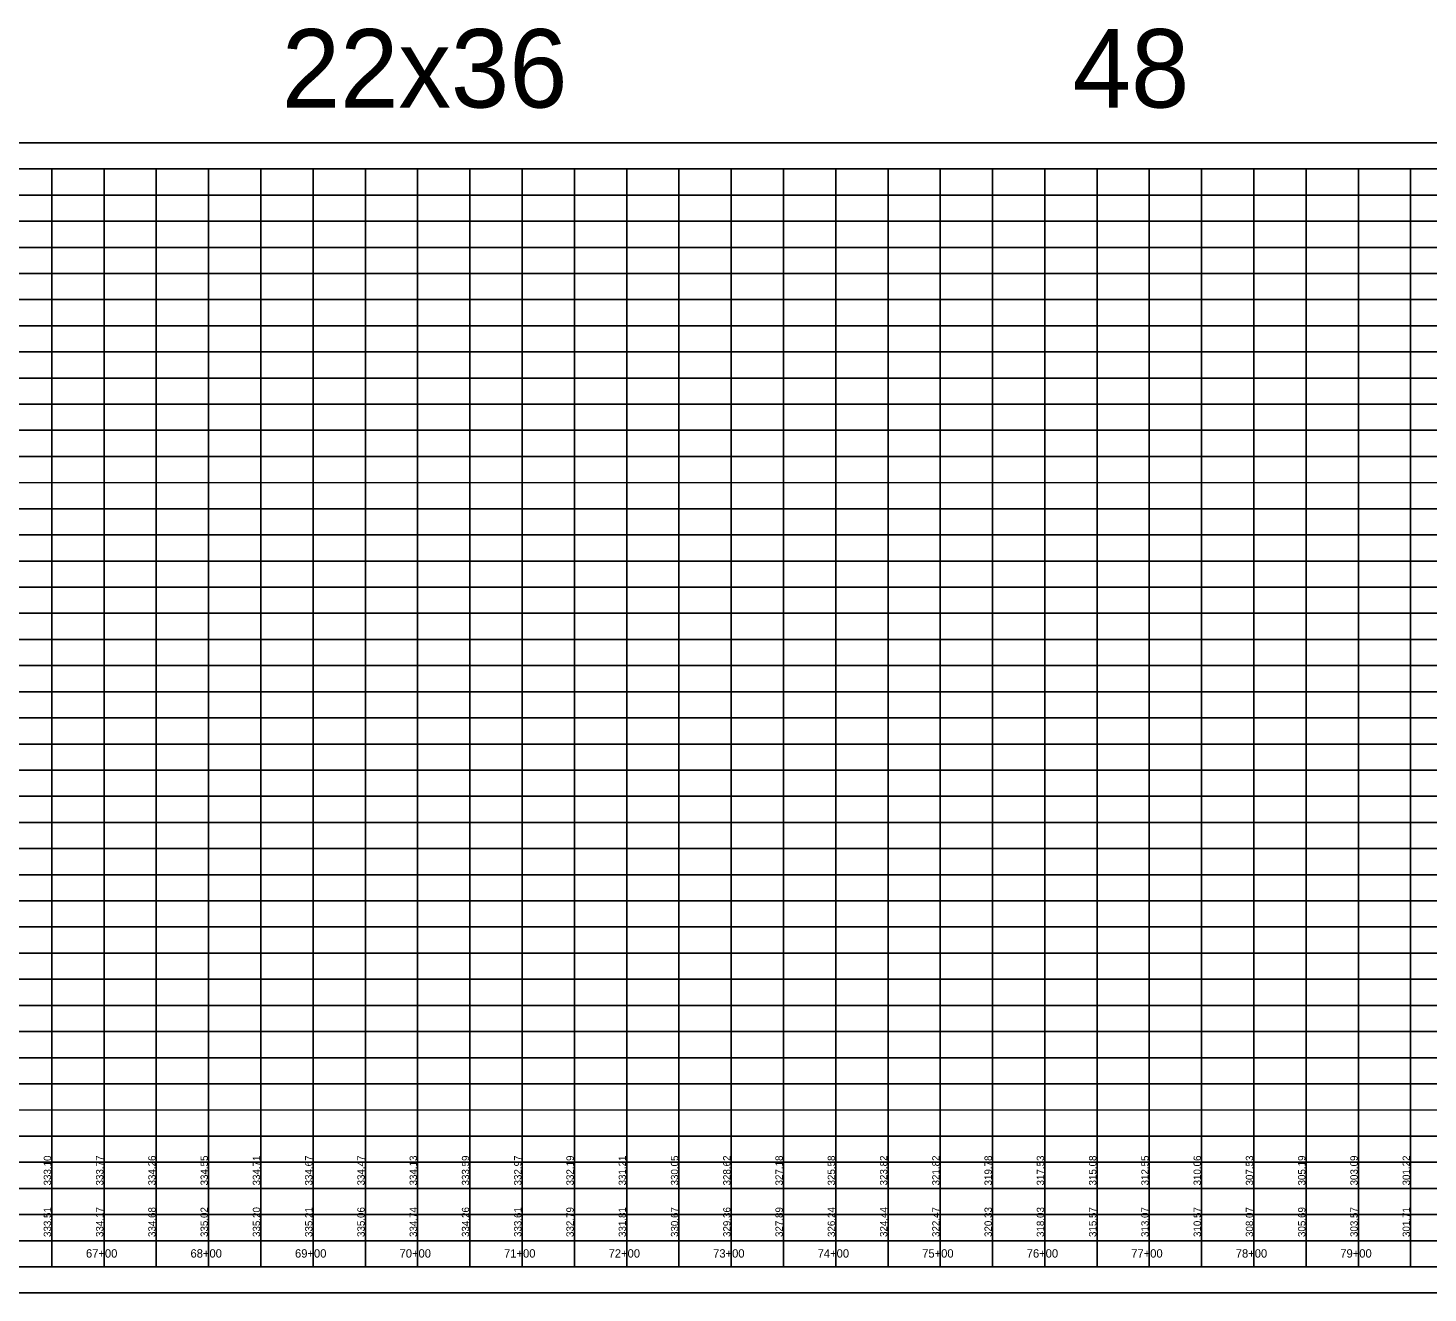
# Model space of a CAD drawing. Extents: x 1873632 to 1926512, y 813126 to 836257.
# Drawn here: x 1884990 to 1886329, y 831005 to 832214 of the extents above; entities that cross this region are included whole.
import ezdxf

# ---------------------------------------------------------------- set-up
doc = ezdxf.new("R2010")
doc.units = 0
for name, color, linetype in [('RD_DDB_StaTX', 7, 'Continuous'), ('RD_DDB_StripGrade', 7, 'Continuous'), ('RD_PD_WallFill', 7, 'Continuous'), ('RD_SHT_IplotShp', 7, 'Continuous')]:
    doc.layers.add(name, color=color, linetype=linetype)

msp = doc.modelspace()

# ---------------------------------------------------------------- linework, layer by layer
at = {"layer": 'RD_PD_WallFill'}
for p, q in [((1883662.8, 832079.6), (1889012.8, 832079.6)), ((1883662.8, 832079.6), (1885412.8, 832079.6)), ((1885012.8, 831029.5), (1885012.8, 832079.6)), ((1885012.8, 831029.5), (1885012.8, 832079.6)), ((1885062.8, 831029.5), (1885062.8, 832079.6)), ((1885062.8, 831029.5), (1885062.8, 832079.6)), ((1885112.8, 831029.6), (1885112.8, 832079.6)), ((1885112.8, 831029.6), (1885112.8, 832079.6)), ((1885162.8, 831029.6), (1885162.8, 832079.6)), ((1885162.8, 831029.6), (1885162.8, 832079.6)), ((1885212.8, 831029.6), (1885212.8, 832079.6)), ((1885212.8, 831029.6), (1885212.8, 832079.6)), ((1885262.8, 831029.6), (1885262.8, 832079.6)), ((1885262.8, 831029.6), (1885262.8, 832079.6)), ((1885312.8, 831029.6), (1885312.8, 832079.6)), ((1885312.8, 831029.6), (1885312.8, 832079.6)), ((1885362.8, 831029.6), (1885362.8, 832079.6)), ((1885362.8, 831029.6), (1885362.8, 832079.6)), ((1885412.8, 831029.6), (1885412.8, 832079.6)), ((1885412.8, 831029.6), (1885412.8, 832079.6)), ((1885462.8, 831029.6), (1885462.8, 832079.6)), ((1885462.8, 831029.6), (1885462.8, 832079.6)), ((1885512.8, 831029.6), (1885512.8, 832079.6)), ((1885512.8, 831029.6), (1885512.8, 832079.6)), ((1885562.8, 831029.6), (1885562.8, 832079.6)), ((1885562.8, 831029.6), (1885562.8, 832079.6)), ((1885612.8, 831029.6), (1885612.8, 832079.6)), ((1885612.8, 831029.6), (1885612.8, 832079.6)), ((1885662.8, 831029.6), (1885662.8, 832079.6)), ((1885662.8, 831029.6), (1885662.8, 832079.6)), ((1885712.8, 831029.6), (1885712.8, 832079.6)), ((1885712.8, 831029.6), (1885712.8, 832079.6)), ((1885762.8, 831029.6), (1885762.8, 832079.6)), ((1885762.8, 831029.6), (1885762.8, 832079.6)), ((1885812.8, 831029.6), (1885812.8, 832079.6)), ((1885812.8, 831029.6), (1885812.8, 832079.6)), ((1885862.8, 831029.6), (1885862.8, 832079.6)), ((1885862.8, 831029.6), (1885862.8, 832079.6)), ((1885912.8, 831029.6), (1885912.8, 832079.6)), ((1885912.8, 831029.6), (1885912.8, 832079.6)), ((1885962.8, 831029.6), (1885962.8, 832079.6)), ((1885962.8, 831029.6), (1885962.8, 832079.6)), ((1886012.8, 831029.6), (1886012.8, 832079.6)), ((1886012.8, 831029.6), (1886012.8, 832079.6)), ((1886062.8, 831029.6), (1886062.8, 832079.6)), ((1886062.8, 831029.6), (1886062.8, 832079.6)), ((1886112.8, 831029.6), (1886112.8, 832079.6)), ((1886112.8, 831029.6), (1886112.8, 832079.6)), ((1886162.8, 831029.6), (1886162.8, 832079.6)), ((1886162.8, 831029.6), (1886162.8, 832079.6)), ((1886212.8, 831029.6), (1886212.8, 832079.6)), ((1886212.8, 831029.6), (1886212.8, 832079.6)), ((1886262.8, 831029.6), (1886262.8, 832079.6)), ((1886262.8, 831029.6), (1886262.8, 832079.6)), ((1886312.8, 831029.6), (1886312.8, 832079.6)), ((1886312.8, 831029.6), (1886312.8, 832079.6)), ((1884112.8, 832054.6), (1889012.8, 832054.6)), ((1884112.8, 832054.6), (1889012.8, 832054.6)), ((1884112.8, 832029.6), (1889012.8, 832029.6)), ((1884112.8, 832004.6), (1889012.8, 832004.6)), ((1884112.8, 831979.6), (1889012.8, 831979.6)), ((1884112.8, 831954.6), (1889012.8, 831954.6)), ((1883662.8, 831929.6), (1889012.8, 831929.6)), ((1883662.8, 831904.6), (1889012.8, 831904.5)), ((1883662.8, 831879.6), (1889012.8, 831879.6)), ((1883662.8, 831854.6), (1889012.8, 831854.5)), ((1883662.8, 831829.6), (1889012.8, 831829.6)), ((1883662.8, 831804.5), (1889012.8, 831804.6)), ((1883662.8, 831779.5), (1889012.8, 831779.6)), ((1883662.8, 831754.6), (1889012.8, 831754.5)), ((1883662.8, 831729.5), (1889012.8, 831729.6)), ((1883662.8, 831704.6), (1889012.8, 831704.6)), ((1883662.8, 831679.6), (1889012.8, 831679.5)), ((1883662.8, 831654.6), (1889012.8, 831654.6)), ((1883662.8, 831629.6), (1889012.8, 831629.5)), ((1883662.8, 831604.6), (1889012.8, 831604.6)), ((1883662.8, 831579.6), (1889012.8, 831579.6)), ((1883662.8, 831554.6), (1889012.8, 831554.5)), ((1883662.8, 831529.6), (1889012.8, 831529.6)), ((1883662.8, 831504.5), (1889012.8, 831504.6)), ((1883662.8, 831479.6), (1889012.8, 831479.6)), ((1883662.8, 831454.6), (1889012.8, 831454.6)), ((1883662.8, 831429.5), (1889012.8, 831429.6)), ((1883662.8, 831404.6), (1889012.8, 831404.5)), ((1883662.8, 831379.6), (1889012.8, 831379.6)), ((1883662.8, 831354.6), (1889012.8, 831354.6)), ((1883662.8, 831329.6), (1889012.8, 831329.5)), ((1883662.8, 831304.6), (1889012.8, 831304.6)), ((1883662.8, 831279.6), (1889012.8, 831279.6)), ((1883662.8, 831254.6), (1889012.8, 831254.6)), ((1883662.8, 831229.6), (1889012.8, 831229.6)), ((1883662.8, 831204.5), (1889012.8, 831204.6)), ((1883662.8, 831179.6), (1889012.8, 831179.5)), ((1883662.8, 831154.6), (1889012.8, 831154.6)), ((1883662.8, 831129.6), (1889012.8, 831129.6)), ((1883662.8, 831104.6), (1889012.8, 831104.6)), ((1883662.8, 831079.6), (1889012.8, 831079.6)), ((1883662.8, 831054.5), (1889012.8, 831054.6)), ((1883662.8, 831029.6), (1889012.8, 831029.5)), ((1883662.8, 831029.6), (1889012.8, 831029.5))]:
    msp.add_line(p, q, dxfattribs=at)
at = {"layer": 'RD_SHT_IplotShp'}
msp.add_lwpolyline([(1883637.8, 831004.6), (1889037.8, 831004.6), (1889037.8, 832104.6), (1883637.8, 832104.6)], close=True, dxfattribs=at)

# ---------------------------------------------------------------- texts
at = {"layer": 'RD_DDB_StaTX'}
for s, p in [('67+00', (1885045.5, 831038.4)), ('68+00', (1885145.5, 831038.4)), ('69+00', (1885245.5, 831038.4)), ('70+00', (1885345.5, 831038.4)), ('71+00', (1885445.5, 831038.4)), ('72+00', (1885545.5, 831038.4)), ('73+00', (1885645.5, 831038.4)), ('74+00', (1885745.5, 831038.4)), ('75+00', (1885845.5, 831038.4)), ('76+00', (1885945.5, 831038.4)), ('77+00', (1886045.5, 831038.4)), ('78+00', (1886145.5, 831038.4)), ('79+00', (1886245.5, 831038.4))]:
    msp.add_text(s, height=8, dxfattribs=at).set_placement(p)
at = {"layer": 'RD_DDB_StripGrade'}
for s, p in [('333.10', (1885012.1, 831107.4)), ('333.77', (1885062.1, 831107.4)), ('334.26', (1885112.1, 831107.4)), ('334.55', (1885162.1, 831107.4)), ('334.71', (1885212.1, 831107.4)), ('334.67', (1885262.1, 831107.4)), ('334.47', (1885312.1, 831107.4)), ('334.13', (1885362.1, 831107.4)), ('333.59', (1885412.1, 831107.4)), ('332.97', (1885462.1, 831107.4)), ('332.19', (1885512.1, 831107.4)), ('331.21', (1885562.1, 831107.4)), ('330.05', (1885612.1, 831107.4)), ('328.62', (1885662.1, 831107.4)), ('327.18', (1885712.1, 831107.4)), ('325.58', (1885762.1, 831107.4)), ('323.82', (1885812.1, 831107.4)), ('321.82', (1885862.1, 831107.4)), ('319.78', (1885912.1, 831107.4)), ('317.53', (1885962.1, 831107.4)), ('315.08', (1886012.1, 831107.4)), ('312.55', (1886062.1, 831107.4)), ('310.06', (1886112.1, 831107.4)), ('307.53', (1886162.1, 831107.4)), ('305.19', (1886212.1, 831107.4)), ('303.09', (1886262.1, 831107.4)), ('301.22', (1886312.1, 831107.4)), ('333.51', (1885012.1, 831058.1)), ('334.17', (1885062.1, 831058.1)), ('334.68', (1885112.1, 831058.1)), ('335.02', (1885162.1, 831058.1)), ('335.20', (1885212.1, 831058.1)), ('335.21', (1885262.1, 831058.1)), ('335.06', (1885312.1, 831058.1)), ('334.74', (1885362.1, 831058.1)), ('334.26', (1885412.1, 831058.1)), ('333.61', (1885462.1, 831058.1)), ('332.79', (1885512.1, 831058.1)), ('331.81', (1885562.1, 831058.1)), ('330.67', (1885612.1, 831058.1)), ('329.36', (1885662.1, 831058.1)), ('327.89', (1885712.1, 831058.1)), ('326.24', (1885762.1, 831058.1)), ('324.44', (1885812.1, 831058.1)), ('322.47', (1885862.1, 831058.1)), ('320.33', (1885912.1, 831058.1)), ('318.03', (1885962.1, 831058.1)), ('315.57', (1886012.1, 831058.1)), ('313.07', (1886062.1, 831058.1)), ('310.57', (1886112.1, 831058.1)), ('308.07', (1886162.1, 831058.1)), ('305.69', (1886212.1, 831058.1)), ('303.57', (1886262.1, 831058.1)), ('301.71', (1886312.1, 831058.1))]:
    msp.add_text(s, height=7, rotation=90, dxfattribs=at).set_placement(p)
at = {"layer": 'RD_PD_WallFill'}
for s, p in [('22x36', (1885232.9, 832138.3)), ('22x36', (1885232.9, 832138.3)), ('48', (1885989.5, 832138.3)), ('48', (1885989.5, 832138.3))]:
    msp.add_text(s, height=75, dxfattribs=at).set_placement(p)

doc.saveas('drawing.dxf')
